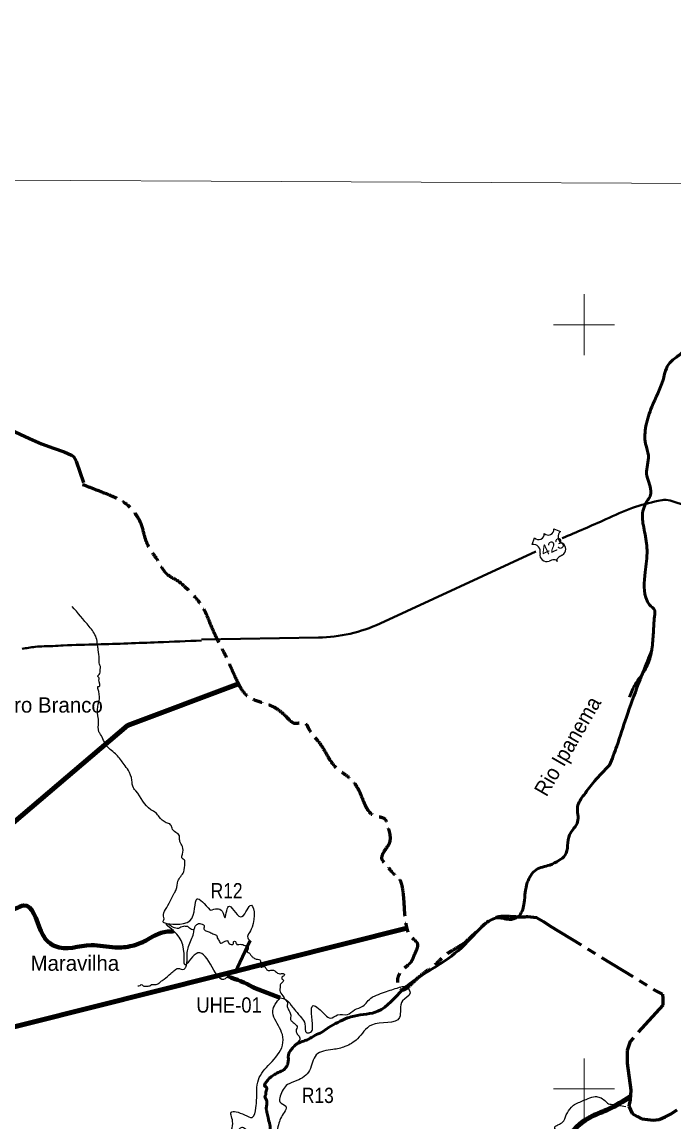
# Model space of a CAD drawing. Extents: x 553962 to 842807, y 8883888 to 9032388.
# Drawn here: x 681625 to 702940, y 8973918 to 9009903 of the extents above; entities that cross this region are included whole.
import ezdxf
from ezdxf.enums import TextEntityAlignment as Align

# ---------------------------------------------------------------- set-up
doc = ezdxf.new("R2010")
doc.units = 0
doc.header["$LTSCALE"] = 200
doc.linetypes.add('LONG_DASH_SHORT_DASH', pattern=[9.9, 6, -1.2, 1.5, -1.2])
for name, color, linetype, lineweight in [('1', 7, 'Continuous', 13), ('12', 7, 'Continuous', 25), ('2', 7, 'Continuous', 13), ('24', 7, 'Continuous', 25), ('48', 7, 'Continuous', 25), ('50', 7, 'Continuous', 80), ('51', 7, 'Continuous', 25), ('7', 7, 'LONG_DASH_SHORT_DASH', 60), ('9', 7, 'Continuous', 90)]:
    doc.layers.add(name, color=color, linetype=linetype, lineweight=lineweight)
for name, color, linetype in [('41', 7, 'Continuous'), ('49', 7, 'Continuous'), ('53', 7, 'Continuous')]:
    doc.layers.add(name, color=color, linetype=linetype)

msp = doc.modelspace()

# ---------------------------------------------------------------- linework, layer by layer
at = {"layer": '1'}
msp.add_lwpolyline([(565303.2, 9005146.6), (664889.8, 9004806.7), (719872.1, 9004543.9), (790635.8, 9004109)], dxfattribs=at)
at = {"layer": '12', "lineweight": 40}
for p, q in [((693333.8, 8990229.2), (698427.6, 8992584.9)), ((687489.1, 8989696.7), (691313.5, 8989763.9))]:
    msp.add_line(p, q, dxfattribs=at)
msp.add_arc((691225.7, 8994763.1), 5000, 271.00622, 294.93643, dxfattribs=at)
for points in [[(699285.5, 8993014.3), (700711.7, 8993635.6), (701584.6, 8994007.8), (702420.2, 8994236.9), (702677.6, 8994271.5), (702949.6, 8994208.3), (703922.6, 8993864.7), (704723.8, 8993521.1), (705539.4, 8992862.6)], [(681628.4, 8989393), (682053.9, 8989462), (682636.7, 8989487.9), (682975.5, 8989505.1), (684088, 8989542.5), (686074.8, 8989611.5), (687496.8, 8989669)]]:
    msp.add_spline(points, degree=3, dxfattribs=at)
at = {"layer": '2'}
for p, q in [((700000, 8999000), (700000, 9001000)), ((699000, 9000000), (701000, 9000000)), ((700000, 8974000), (700000, 8976000)), ((699000, 8975000), (701000, 8975000))]:
    msp.add_line(p, q, dxfattribs=at)
at = {"layer": '24', "lineweight": 53}
for points in [[(701485.3, 8987819.6), (701680.1, 8988244.2), (701892.7, 8988551.5), (702105.4, 8988953.4), (702223.5, 8989449.8), (702270.7, 8989993.5), (702309.6, 8990518.5), (702309.6, 8990655.6), (702138.3, 8990838.4), (702058.3, 8990964.1), (702001.2, 8991901.1), (702058.3, 8992621), (701978.4, 8993226.6), (701909.9, 8993763.7), (702081.2, 8994266.4), (702161.1, 8994392.1), (702183.9, 8994563.5), (702046.9, 8995123.4), (702104, 8995717.6), (702012.6, 8996106.1), (702024.1, 8996688.9), (702218.2, 8997317.3), (702583.6, 8998197.2), (702800.6, 8998757.1), (703097.5, 8998997), (703668.5, 8999499.8), (703862.6, 8999602.7), (704182.3, 9000288.2), (704330.8, 9000551.1), (704730.5, 9000813.9), (705038.8, 9000962.4), (705347.1, 9001213.8), (705381.3, 9001270.9), (705655.4, 9001636.6), (705815.3, 9002230.8), (706009.4, 9002665), (706066.5, 9002984.9), (706671.7, 9003224.9), (706877.3, 9003270.6), (707231.3, 9003761.9), (707585.3, 9004161.9), (707722.3, 9004687.5), (707825.1, 9005041.7), (708019.2, 9005304.5), (708236.2, 9005453.1), (708384.6, 9005795.9), (708384.6, 9006332.9), (708430.3, 9006618.6), (708841.4, 9007144.2), (708978.5, 9007384.2), (709047, 9007818.4), (709081.2, 9008046.9), (708944.2, 9008412.6), (708955.6, 9008766.8), (708921.3, 9009223.9), (709252.5, 9009509.5), (709549.4, 9009646.7), (709720.7, 9009715.2), (709869.2, 9009875.2), (709949.1, 9010035.2), (709949.1, 9010389.4), (710097.6, 9010549.4), (710234.6, 9011017.8), (710325.9, 9011189.2), (710588.6, 9011383.5), (710679.9, 9011589.2), (710679.9, 9011772), (710531.5, 9012137.7), (710394.5, 9012434.8), (710405.9, 9012606.2), (710508.6, 9012777.6), (710885.5, 9013451.7), (711056.8, 9013646), (711102.5, 9013874.5), (711068.2, 9014365.8), (711022.5, 9014708.7), (710805.5, 9015188.6), (710759.9, 9015325.7), (710828.4, 9015462.8), (710908.3, 9015599.9), (710817, 9015782.8), (710668.5, 9015942.7), (710394.5, 9016228.4), (710405.9, 9016376.9), (710611.4, 9016708.3), (710634.2, 9017119.7), (710645.7, 9017393.9), (710759.9, 9017599.6), (710896.9, 9017919.5), (710942.6, 9018182.3), (710771.3, 9018513.7)], [(700834.8, 8985588.3), (701069.9, 8986215.3), (701383.2, 8987155.9), (702215.3, 8989348)], [(689736.6, 8973458), (689742.4, 8973643.8), (689727.8, 8973829.6), (689666.9, 8974061.8), (689632.1, 8974244.7), (689611.8, 8974346.9), (689626.3, 8974474.6), (689608.9, 8974654.6), (689568.3, 8974741.7), (689591.5, 8974811.3), (689591.5, 8974898.4), (689617.6, 8974965.2), (689606, 8975066.8), (689562.5, 8975087.1), (689556.7, 8975136.5), (689597.3, 8975206.1), (689678.5, 8975313.6), (689817.8, 8975432.6), (689954.2, 8975513.9), (690148.6, 8975603.8), (690267.5, 8975722.9), (690319.8, 8975833.2), (690337.2, 8976115.9), (690360.4, 8976194.3), (690444.5, 8976310.4), (690543.2, 8976417.8), (690636, 8976487.5), (690836.2, 8976565.9), (690992.9, 8976626.8), (691193.1, 8976748.8), (691428.1, 8976856.2), (691648.6, 8977007.1), (691944.6, 8977175.5), (692269.6, 8977320.7), (692484.3, 8977384.5), (693261.9, 8977541.3), (694071.4, 8978246.7), (695037.6, 8978926), (696003.8, 8979631.4), (696761.1, 8980389.1), (697178.9, 8980598.1), (697622.9, 8980545.8), (697884, 8980676.5), (698040.7, 8981094.5), (698145.1, 8981747.7), (698432.4, 8982165.7), (698876.3, 8982322.4), (699189.7, 8982479.2), (699372.5, 8982636), (699529.2, 8983315.2), (699790.3, 8983733.3), (699790.3, 8984229.7), (699999.2, 8984621.6), (700338.7, 8985065.7), (700834.8, 8985588.3)]]:
    msp.add_spline(points, degree=3, dxfattribs=at)
at = {"layer": '24'}
for points in [[(687252.8, 8980199.7), (687166.4, 8980215.3), (687101.2, 8980261.9), (687040.7, 8980308.5), (686970.8, 8980317.8), (686901, 8980317.8), (686742.7, 8980252.6), (686575, 8980285.2), (686332.9, 8980415.6), (686239.8, 8980462.2), (686267.7, 8980560.1), (686249.1, 8980648.6), (686319, 8980867.6), (686603, 8981398.7), (686663.5, 8981524.5), (686724, 8981794.7), (686910.3, 8982102.2), (686952.2, 8982386.4), (686942.9, 8982470.3), (686854.4, 8982554.2), (686873, 8982684.6), (686868.4, 8982926.9), (686789.2, 8983094.6), (686770.6, 8983220.4), (686770.6, 8983276.3), (686649.6, 8983392.8), (686528.5, 8983527.9), (686481.9, 8983644.4), (686337.6, 8983709.6), (686104.8, 8983905.3), (686007, 8984026.5), (685834.7, 8984133.6), (685350.5, 8984748.6), (685266.7, 8984851.1), (685215.5, 8985102.7), (685103.7, 8985419.5), (684959.4, 8985615.2), (684717.3, 8985927.4), (684400.6, 8986216.2), (684191.1, 8986598.3), (684139.9, 8986682.2), (684130.6, 8986994.3), (684088.7, 8987409), (684153.8, 8987749.1), (684107.3, 8988103.2), (684107.3, 8988163.8), (684139.9, 8988163.8), (684139.9, 8988382.8), (684144.5, 8988434), (684116.6, 8988480.6), (684102.6, 8988494.6), (684144.5, 8988555.1), (684177.1, 8988713.5), (684186.5, 8988820.7), (684158.5, 8988895.2), (684144.5, 8989067.6), (684116.6, 8989361.2), (684093.3, 8989528.9), (684051.4, 8989761.8), (683823.3, 8990125.3), (683259.9, 8990786.8)], [(685407.2, 8978371.7), (685484.9, 8978382.8), (685523.7, 8978416.1), (685584.8, 8978371.7), (685690.2, 8978360.6), (685806.8, 8978377.2), (685862.3, 8978410.5), (685940.1, 8978410.5), (686067.7, 8978438.3), (686162.1, 8978510.4), (686267.6, 8978588.1), (686495.2, 8978776.9), (686622.8, 8978887.9), (686722.7, 8978943.4), (686828.2, 8978915.7), (686922.6, 8978921.2), (686978.1, 8978987.8), (687011.4, 8979109.9), (687022.5, 8979248.7), (687028, 8979465.2), (687066.9, 8979653.9), (687155.7, 8979876), (687233.4, 8980086.9), (687261.2, 8980242.3), (687288.9, 8980320.1), (687366.7, 8980392.2), (687433.3, 8980414.4), (687511, 8980386.7), (687583.1, 8980342.2), (687572, 8980236.8), (687633.1, 8980175.7), (687760.8, 8980125.8), (687899.6, 8980059.2), (687993.9, 8980009.2), (688005, 8979937), (688043.9, 8979881.5), (688077.2, 8979826), (688110.5, 8979765), (688166, 8979776.1), (688243.7, 8979820.5), (688343.6, 8979848.2), (688376.9, 8979776.1), (688432.4, 8979737.2), (688532.4, 8979737.2), (688554.6, 8979826), (688599, 8979820.5), (688632.3, 8979742.8), (688754.4, 8979731.7), (688920.9, 8979687.2), (689020.8, 8979620.6), (689009.7, 8979548.5), (688982, 8979481.8), (689059.7, 8979443), (689109.7, 8979370.8), (689176.3, 8979304.2)], [(689176.3, 8979304.2), (689281.7, 8979243.2), (689370.6, 8979237.6), (689415, 8979209.8), (689415, 8979115.5), (689426.1, 8979054.4), (689448.3, 8978987.8), (689537.1, 8979010), (689575.9, 8978982.3), (689631.5, 8978899), (689731.4, 8978876.8), (689831.3, 8978887.9), (689909, 8978843.5), (690053.3, 8978765.8), (690158.8, 8978776.9), (690203.2, 8978743.6), (690169.9, 8978688.1), (690125.5, 8978671.4), (690136.6, 8978582.6), (690175.4, 8978548), (690125.5, 8978475.8), (690075.5, 8978431.3), (690064.4, 8978314.7), (690053.3, 8978214.7), (690147.7, 8978048.1), (690236.5, 8977914.8), (690308.7, 8977809.3), (690297.6, 8977737.1), (690308.7, 8977659.3), (690375.3, 8977515), (690408.6, 8977381.7), (690397.5, 8977292.8), (690441.9, 8977215.1), (690547.3, 8977126.2), (690619.5, 8977015.1), (690591.8, 8976942.9), (690591.8, 8976870.7), (690641.7, 8976770.8), (690708.3, 8976665.2), (690702.8, 8976609.7), (690658.4, 8976554.2), (690627.7, 8976484.1)], [(698620.9, 8972830.7), (698703.3, 8972970.3), (698754.1, 8973135.3), (698804.8, 8973370.2), (699039.5, 8973503.4), (699102.9, 8973624), (699039.5, 8973725.5), (699147.3, 8973827.1), (699299.6, 8973909.6), (699420.1, 8974150.7), (699585, 8974398.2), (699686.5, 8974487.1), (699857.8, 8974569.6), (700136.8, 8974683.8), (700365.2, 8974747.3), (700517.4, 8974721.9), (700676, 8974620.3), (700771.1, 8974531.5), (700910.7, 8974493.4), (701361, 8974430)]]:
    msp.add_spline(points, degree=3, dxfattribs=at)
at = {"layer": '48'}
for p, q in [((699016.6, 8993318.3), (699228.8, 8993240.2)), ((698303.6, 8992812.7), (698381.8, 8993024.9))]:
    msp.add_line(p, q, dxfattribs=at)
for centre, radius, start, end in [((698512.4, 8993159.1), 187.2, 225.75891, 3.84037), ((698829.8, 8993305.7), 187.2, 225.75891, 3.84037), ((699378.2, 8993064.8), 230.3, 130.42737, 247.22754), ((698340.3, 8992585.3), 230.3, 342.37174, 99.1685), ((699176.9, 8992657.7), 224.7, 300.14186, 60.06231), ((698780.8, 8992474.7), 224.7, 169.53697, 289.45741), ((699207.2, 8992297.1), 94.4, 131.87009, 207.10619), ((699538.1, 8991928.5), 589.7, 114.89907, 131.90593), ((699102.1, 8991727), 589.7, 97.69335, 114.70021), ((699035.9, 8992217.9), 94.4, 22.49309, 97.72919)]:
    msp.add_arc(centre, radius, start, end, dxfattribs=at)
at = {"layer": '50'}
msp.add_line((689209.2, 8978309.7), (690059.7, 8977980.8), dxfattribs=at)
for points in [[(679249.2, 8980359.8), (680020.1, 8980653.9), (680410.9, 8980689.4), (680836.6, 8980780.7), (681407.5, 8980897.3), (681677.8, 8981003.8), (682241.4, 8980172), (682422.6, 8979867.7), (682703.8, 8979664.9), (683881.3, 8979700.3), (684673.2, 8979629.3), (685224.3, 8979680), (685679.8, 8979857.5), (685970, 8980019.7), (686380.6, 8980146.5), (686588.5, 8980155.5)], [(688351.4, 8978684.7), (689176.4, 8978331.2), (689240.7, 8978294.5)]]:
    msp.add_spline(points, degree=3, dxfattribs=at)
at = {"layer": '51', "lineweight": 53}
msp.add_line((688586.7, 8978784), (689079.8, 8979859.2), dxfattribs=at)
at = {"layer": '51'}
msp.add_line((689079.8, 8979844), (688586.7, 8978768.8), dxfattribs=at)
for points in [[(688586.7, 8978768.8), (688501.4, 8978794.2), (688261.7, 8978602.2), (687374.7, 8979449.4), (686971.5, 8979056.1), (686830.4, 8979852.9), (686346.6, 8980387.5), (687112.6, 8980498.4), (687344.4, 8981214.6), (687779.2, 8980843.1)], [(687779.2, 8980843.1), (688170.2, 8980812.7), (688261, 8980594.6), (688372.6, 8980972.5), (688765.7, 8980629.6), (689088.2, 8981002.8), (689148.7, 8980286.6), (689019.5, 8979904.8), (689079.8, 8979844)], [(690059.7, 8977980.8), (690265.3, 8977909.8), (690476.4, 8977666.3), (690566.9, 8977554.8), (690763, 8977321.5), (690872.3, 8977129.6), (690932.8, 8976837.1), (691094.1, 8976877.4), (691124.6, 8977022.2), (691144.5, 8977724.7), (691534.5, 8977422.9), (691709, 8977311.1), (691940.8, 8977422.1), (692263.3, 8977432.2), (692495.2, 8977583.4), (692767.3, 8977704.5), (692908.4, 8977845.7), (693069.7, 8977997), (693150.3, 8978037.3), (693664.4, 8978229), (693886.2, 8978299.6), (694208.7, 8978329.8), (694309.5, 8978128.1), (694068.8, 8977884.3), (693966.8, 8977331.3), (693049.6, 8977089.2), (692593.9, 8976641.8), (692183.7, 8976383.2), (691788.1, 8976286.8), (691242.4, 8976114.4), (691023.3, 8975607.3), (690608.3, 8975272.6), (690308, 8975140.7), (690063.5, 8974760.4), (690059, 8974572.7), (690249.8, 8974440.9), (690105.4, 8974085.9), (690025.8, 8973877.9), (689936.9, 8973401.2), (689945, 8973337.1), (690025.6, 8973216), (690267.6, 8973074.8), (690074.8, 8972468.1), (689723.2, 8972096.4), (689835.8, 8971910.2), (689886.3, 8971763.1), (689941.7, 8971646.5), (689842.2, 8971403), (689577.2, 8971190), (689352.2, 8971012.6), (689237.1, 8970936.5), (689182.2, 8970845.2)], [(688870.4, 8971276.3), (688925.3, 8971357.4), (689000.1, 8971489.3), (689119.4, 8971839.2), (689188.6, 8972179), (689147.8, 8972452.9), (688735.4, 8972903.3), (689215.8, 8973208.5), (689259.6, 8973377.4), (689088.2, 8973538.8), (688806, 8973740.5), (688618.6, 8973563.6), (688453.2, 8973448), (688513.7, 8973871.6), (688463.3, 8974234.7), (688896.7, 8974154.1), (689148.7, 8974063.3), (689272.8, 8974385.1), (689301.5, 8974877.1), (689330.1, 8975223.2), (689669.9, 8975764.6), (690114.2, 8976347.8), (690153.4, 8976697.7), (690045.8, 8976998.4), (689825.3, 8977559.9), (690059.7, 8977980.8)]]:
    msp.add_spline(points, degree=3, dxfattribs=at)
at = {"layer": '7'}
for points in [[(681254.3, 8996559), (681874.7, 8996282.7), (682263.6, 8996108.4), (682659.2, 8995956.7), (683003.4, 8995837.6), (683247.7, 8995729), (683305.4, 8995683.4), (683391.2, 8995534.3), (683640.1, 8994841.9)], [(698156.4, 8980636.2), (698446.2, 8980606.7), (698674.9, 8980481), (698885.8, 8980337.8), (702385.1, 8978187.2), (702561.1, 8978097.3), (702577.6, 8977955.8), (702575.7, 8977743.8), (701504.8, 8976551.4), (701486.5, 8976480.9), (701413.8, 8976251.8), (701410.3, 8975845.4), (701526.5, 8974960.9), (701506, 8974643), (701468.9, 8974431.2), (701572.9, 8974200.6), (701748.8, 8974093.1), (701889.6, 8974021.2), (702260.5, 8973982.6), (702455.1, 8973998.6), (702650.3, 8974085.3), (702827.8, 8974172.1), (703041.1, 8974311.7)]]:
    msp.add_lwpolyline(points, dxfattribs=at)
msp.add_spline([(683598.6, 8994777.1), (684397.7, 8994464.4), (685057.9, 8994117), (685335.8, 8993804.3), (685509.6, 8993491.6), (685648.5, 8993005.2), (685787.5, 8992692.5), (686065.5, 8992275.5), (686343.4, 8991858.6), (686725.6, 8991615.4), (687073, 8991302.7), (687420.5, 8990920.5), (687906.9, 8989912.9), (688323.8, 8989079.1), (688636.5, 8988384.2), (688984, 8987863), (689435.6, 8987654.6), (689817.8, 8987515.6), (690269.5, 8987168.1), (690582.2, 8986959.7), (690825.4, 8986994.4), (691033.9, 8986716.5), (691311.8, 8986369), (691902.5, 8985500.4), (692354.1, 8985153), (692666.8, 8984701.3), (692875.3, 8984214.9), (693158.7, 8983934.4), (693502.3, 8983815), (693545.2, 8983676.6), (693602.5, 8983504.7), (693621.6, 8983017.8), (693570.2, 8982929.4), (693397.3, 8982487.9), (693500.7, 8982373.5), (693769.5, 8982043.9), (693907.8, 8981934.1), (694056.6, 8981574.3), (694126.1, 8980775.2), (694195.6, 8980288.8), (694332.5, 8979985.6), (694542.5, 8979770.8), (694432.7, 8979351), (694365.9, 8979193.5), (694122.6, 8978945.4), (693898.3, 8978539.8), (694012.8, 8978253.5), (694475.7, 8978549.3), (695243.9, 8979169.6), (695396.6, 8979322.3), (696002.5, 8979718.4), (696732.6, 8980376.8), (697123.8, 8980615.4), (697739.5, 8980636.2), (698156.4, 8980636.2)], degree=3, dxfattribs=at)
at = {"layer": '9'}
for points in [[(672140.1, 8985527), (681326.7, 8983693), (685074.1, 8986884.1), (688700.7, 8988246.5)], [(658746.8, 8975176), (664691.5, 8973777.5), (669474.2, 8974039.3), (694202.6, 8980257.8)]]:
    msp.add_lwpolyline(points, dxfattribs=at)
msp.add_spline([(697027.9, 8970867.6), (697532.6, 8971580), (697963, 8971962.8), (698800.9, 8972272.6), (699330.5, 8973086.5), (699961.7, 8973926.4), (700266.1, 8974105.8), (700799.1, 8974337.4), (701512.5, 8974742.8)], degree=3, dxfattribs=at)

# ---------------------------------------------------------------- texts
at = {"layer": '41'}
for s, p in [('Ouro Branco', (680474.5, 8987309.9)), ('Maravilha', (681902.6, 8978864.1))]:
    msp.add_text(s, height=500, dxfattribs=at).set_placement(p)
at = {"layer": '48'}
msp.add_text('423', height=350, rotation=24.8, dxfattribs=at).set_placement((699035.7, 8992577.6), align=Align.CENTER)
at = {"layer": '49', "width": 0.95}
msp.add_text('Rio Ipanema', height=500, rotation=59.912, dxfattribs=at).set_placement((699675.8, 8986088.2), align=Align.CENTER)
at = {"layer": '53'}
for s, width, p in [('R12', 0.85, (688313.7, 8981233.7)), ('UHE-01', 0.9, (688394.5, 8977495.3)), ('R13', 0.85, (691296, 8974539.5))]:
    msp.add_text(s, height=500, dxfattribs=dict(at, width=width)).set_placement(p, align=Align.CENTER)

doc.saveas('drawing.dxf')
